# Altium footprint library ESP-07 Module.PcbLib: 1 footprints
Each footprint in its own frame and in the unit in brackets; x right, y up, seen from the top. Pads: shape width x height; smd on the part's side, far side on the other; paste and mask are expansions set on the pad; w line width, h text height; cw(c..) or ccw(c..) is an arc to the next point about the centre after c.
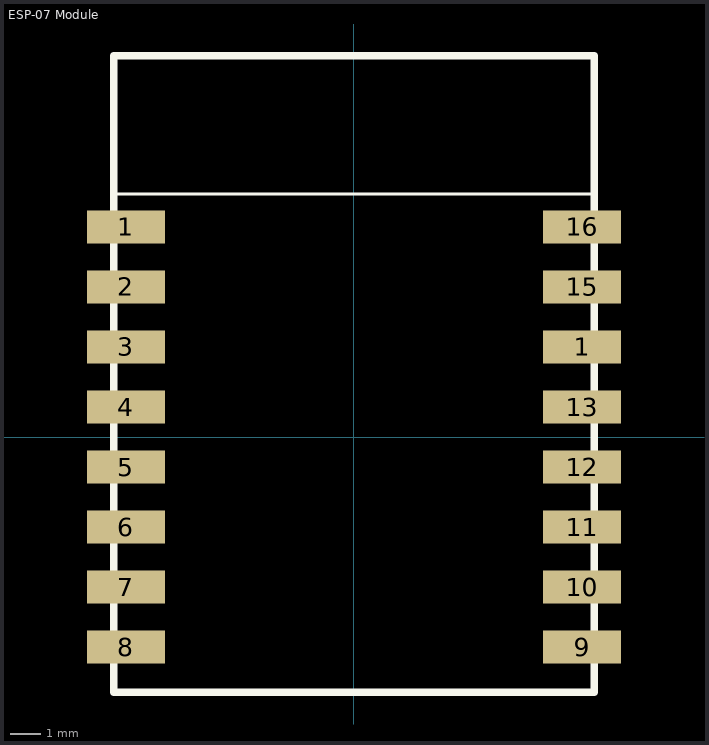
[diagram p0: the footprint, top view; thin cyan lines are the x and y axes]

## ESP-07 Module [mm]
pads (16):
  rect 2.6x1.1 smd: 1(-7.6,7) 1(7.6,3) 2(-7.6,5) 3(-7.6,3) 4(-7.6,1) 5(-7.6,-1) 6(-7.6,-3) 7(-7.6,-5) 8(-7.6,-7) 9(7.6,-7) 10(7.6,-5) 11(7.6,-3) 12(7.6,-1) 13(7.6,1) 15(7.6,5) 16(7.6,7)
Top Overlay:
  lines w0.1: -8,8.1 8,8.1
  lines w0.254: -8,-8.5 8,-8.5 8,12.7 -8,12.7 -8,-8.5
